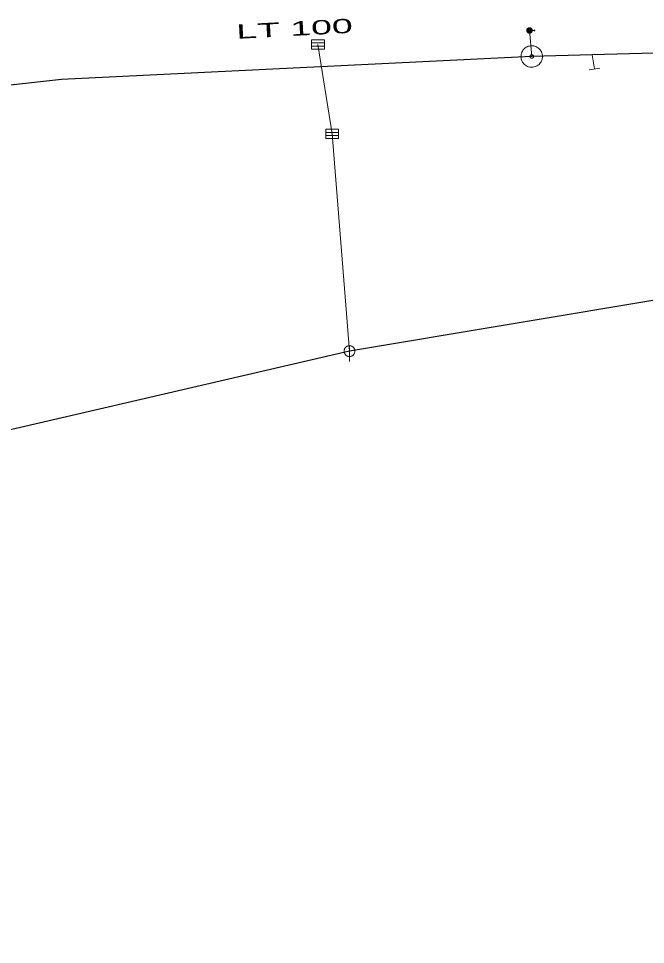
# Model space of a CAD drawing. Extents: x -687515 to -686506, y -974029 to -973461.
# Drawn here: x -686720.18 to -686691.06, y -973717.75 to -973674.72 of the extents above; entities that cross this region are included whole.
import ezdxf
from ezdxf.enums import TextEntityAlignment as Align

# ---------------------------------------------------------------- set-up
doc = ezdxf.new("R2010")
doc.units = 0
doc.header["$LTSCALE"] = 0.27
for name, color, linetype, lineweight in [('1', 7, 'Continuous', 13), ('11', 7, 'Continuous', 13), ('14', 7, 'Continuous', 25), ('17', 7, 'Continuous', 25), ('22', 7, 'Continuous', 13), ('34', 7, 'Continuous', 13), ('47', 7, 'Continuous', 13), ('9', 7, 'Continuous', 13)]:
    doc.layers.add(name, color=color, linetype=linetype, lineweight=lineweight)

msp = doc.modelspace()

# ---------------------------------------------------------------- linework, layer by layer
at = {"layer": '11'}
msp.add_lwpolyline([(-686706.28, -973675.92), (-686705.62, -973680.08), (-686704.81, -973690.17)], dxfattribs=at)
at = {"layer": '14', "lineweight": 13}
for p, q in [((-686696.345, -973676.48), (-686696.449, -973675.269)), ((-686693.532, -973676.405), (-686693.429, -973677.059))]:
    msp.add_line(p, q, dxfattribs=at)
at = {"layer": '14'}
for p, q in [((-686672.372, -973684.756), (-686704.809, -973690.17)), ((-686704.809, -973690.17), (-686742.511, -973698.919))]:
    msp.add_line(p, q, dxfattribs=at)
at = {"layer": '17'}
for points in [[(-686506.346, -973717.746), (-686529.344, -973710.524), (-686536.247, -973707.872), (-686555.026, -973699.577), (-686572.978, -973698.129), (-686583.112, -973698.418), (-686615.962, -973695.359), (-686637.993, -973681.581), (-686653.818, -973675.34), (-686693.532, -973676.405), (-686696.345, -973676.48)], [(-686696.345, -973676.48), (-686718.181, -973677.546), (-686724.343, -973678.231)]]:
    msp.add_lwpolyline(points, dxfattribs=at)
at = {"layer": '22'}
for p, q in [((-686706.575, -973675.849), (-686705.977, -973675.849)), ((-686706.575, -973675.995), (-686705.977, -973675.995)), ((-686705.915, -973680.009), (-686705.317, -973680.009)), ((-686705.915, -973680.154), (-686705.317, -973680.154)), ((-686704.809, -973689.918), (-686704.81, -973690.662))]:
    msp.add_line(p, q, dxfattribs=at)
for points in [[(-686706.575, -973675.703), (-686705.977, -973675.703), (-686705.977, -973676.14), (-686706.575, -973676.14)], [(-686705.915, -973679.863), (-686705.317, -973679.863), (-686705.317, -973680.299), (-686705.915, -973680.299)], [(-686704.558, -973690.17), (-686704.559, -973690.144), (-686704.563, -973690.118), (-686704.569, -973690.092), (-686704.579, -973690.068), (-686704.591, -973690.044), (-686704.605, -973690.022), (-686704.622, -973690.001), (-686704.64, -973689.983), (-686704.661, -973689.966), (-686704.683, -973689.952), (-686704.707, -973689.94), (-686704.731, -973689.93), (-686704.757, -973689.924), (-686704.783, -973689.92), (-686704.809, -973689.918), (-686704.835, -973689.919), (-686704.861, -973689.923), (-686704.887, -973689.929), (-686704.912, -973689.939), (-686704.935, -973689.951), (-686704.957, -973689.965), (-686704.978, -973689.982), (-686704.996, -973690), (-686705.013, -973690.021), (-686705.027, -973690.043), (-686705.039, -973690.067), (-686705.049, -973690.091), (-686705.056, -973690.117), (-686705.06, -973690.143), (-686705.062, -973690.169), (-686705.061, -973690.195), (-686705.057, -973690.221), (-686705.05, -973690.247), (-686705.04, -973690.272), (-686705.028, -973690.295), (-686705.014, -973690.317), (-686704.997, -973690.338), (-686704.979, -973690.356), (-686704.958, -973690.373), (-686704.936, -973690.387), (-686704.913, -973690.399), (-686704.888, -973690.409), (-686704.862, -973690.416), (-686704.836, -973690.42), (-686704.81, -973690.422), (-686704.784, -973690.421), (-686704.758, -973690.417), (-686704.732, -973690.41), (-686704.708, -973690.4), (-686704.684, -973690.388), (-686704.662, -973690.374), (-686704.641, -973690.357), (-686704.623, -973690.339), (-686704.606, -973690.318), (-686704.592, -973690.296), (-686704.58, -973690.273), (-686704.57, -973690.248), (-686704.564, -973690.222), (-686704.56, -973690.196)]]:
    msp.add_lwpolyline(points, close=True, dxfattribs=at)
at = {"layer": '34'}
msp.add_line((-686693.674, -973677.097), (-686693.183, -973677.02), dxfattribs=at)
at = {"layer": '47'}
for points in [[(-686695.885, -973676.676), (-686695.867, -973676.627), (-686695.854, -973676.576), (-686695.847, -973676.524), (-686695.844, -973676.472), (-686695.848, -973676.42), (-686695.858, -973676.368), (-686695.872, -973676.318), (-686695.892, -973676.269), (-686695.915, -973676.223), (-686695.945, -973676.179), (-686695.978, -973676.139), (-686696.016, -973676.103), (-686696.057, -973676.071), (-686696.102, -973676.043), (-686696.148, -973676.02), (-686696.197, -973676.002), (-686696.248, -973675.989), (-686696.301, -973675.982), (-686696.352, -973675.979), (-686696.404, -973675.983), (-686696.456, -973675.993), (-686696.507, -973676.007), (-686696.555, -973676.026), (-686696.602, -973676.05), (-686696.645, -973676.08), (-686696.685, -973676.113), (-686696.722, -973676.151), (-686696.753, -973676.192), (-686696.781, -973676.237), (-686696.804, -973676.283), (-686696.822, -973676.332), (-686696.835, -973676.383), (-686696.843, -973676.435), (-686696.845, -973676.487), (-686696.841, -973676.539), (-686696.832, -973676.591), (-686696.818, -973676.642), (-686696.799, -973676.69), (-686696.774, -973676.737), (-686696.744, -973676.78), (-686696.711, -973676.82), (-686696.674, -973676.856), (-686696.632, -973676.888), (-686696.587, -973676.916), (-686696.541, -973676.939), (-686696.492, -973676.957), (-686696.441, -973676.97), (-686696.39, -973676.978), (-686696.337, -973676.98), (-686696.285, -973676.976), (-686696.233, -973676.967), (-686696.183, -973676.953), (-686696.135, -973676.933), (-686696.088, -973676.909), (-686696.044, -973676.879), (-686696.004, -973676.846), (-686695.969, -973676.809), (-686695.936, -973676.767), (-686695.908, -973676.722)], [(-686696.269, -973676.512), (-686696.266, -973676.503), (-686696.264, -973676.495), (-686696.263, -973676.487), (-686696.263, -973676.479), (-686696.263, -973676.47), (-686696.265, -973676.461), (-686696.267, -973676.453), (-686696.27, -973676.445), (-686696.274, -973676.438), (-686696.279, -973676.43), (-686696.285, -973676.423), (-686696.291, -973676.418), (-686696.297, -973676.413), (-686696.304, -973676.408), (-686696.312, -973676.404), (-686696.321, -973676.401), (-686696.329, -973676.399), (-686696.337, -973676.398), (-686696.345, -973676.398), (-686696.354, -973676.398), (-686696.363, -973676.4), (-686696.371, -973676.402), (-686696.379, -973676.405), (-686696.387, -973676.409), (-686696.394, -973676.414), (-686696.401, -973676.42), (-686696.406, -973676.426), (-686696.411, -973676.432), (-686696.416, -973676.439), (-686696.42, -973676.447), (-686696.423, -973676.456), (-686696.425, -973676.464), (-686696.426, -973676.472), (-686696.426, -973676.48), (-686696.426, -973676.489), (-686696.425, -973676.497), (-686696.422, -973676.506), (-686696.419, -973676.514), (-686696.415, -973676.522), (-686696.41, -973676.529), (-686696.404, -973676.536), (-686696.398, -973676.541), (-686696.392, -973676.546), (-686696.385, -973676.551), (-686696.377, -973676.555), (-686696.368, -973676.558), (-686696.36, -973676.56), (-686696.352, -973676.561), (-686696.344, -973676.561), (-686696.335, -973676.561), (-686696.327, -973676.56), (-686696.318, -973676.557), (-686696.31, -973676.554), (-686696.303, -973676.55), (-686696.295, -973676.545), (-686696.288, -973676.539), (-686696.283, -973676.533), (-686696.278, -973676.527), (-686696.273, -973676.52)]]:
    msp.add_lwpolyline(points, close=True, dxfattribs=at)
at = {"layer": '9'}
msp.add_line((-686696.323, -973675.269), (-686696.197, -973675.269), dxfattribs=at)
for points in [[(-686696.449, -973675.395), (-686696.436, -973675.394), (-686696.423, -973675.392), (-686696.41, -973675.389), (-686696.398, -973675.384), (-686696.386, -973675.378), (-686696.375, -973675.371), (-686696.365, -973675.363), (-686696.355, -973675.353), (-686696.347, -973675.343), (-686696.34, -973675.332), (-686696.334, -973675.32), (-686696.329, -973675.308), (-686696.326, -973675.295), (-686696.324, -973675.282), (-686696.323, -973675.269), (-686696.323, -973675.256), (-686696.325, -973675.243), (-686696.328, -973675.23), (-686696.333, -973675.218), (-686696.339, -973675.206), (-686696.346, -973675.195), (-686696.354, -973675.185), (-686696.364, -973675.175), (-686696.374, -973675.167), (-686696.385, -973675.16), (-686696.397, -973675.154), (-686696.409, -973675.149), (-686696.422, -973675.146), (-686696.435, -973675.144), (-686696.448, -973675.142), (-686696.461, -973675.143), (-686696.474, -973675.145), (-686696.487, -973675.148), (-686696.499, -973675.153), (-686696.511, -973675.159), (-686696.522, -973675.166), (-686696.532, -973675.174), (-686696.542, -973675.184), (-686696.55, -973675.194), (-686696.557, -973675.205), (-686696.563, -973675.217), (-686696.568, -973675.229), (-686696.571, -973675.242), (-686696.573, -973675.255), (-686696.575, -973675.268), (-686696.574, -973675.281), (-686696.572, -973675.294), (-686696.569, -973675.307), (-686696.564, -973675.319), (-686696.558, -973675.331), (-686696.551, -973675.342), (-686696.543, -973675.352), (-686696.533, -973675.362), (-686696.523, -973675.37), (-686696.512, -973675.377), (-686696.5, -973675.383), (-686696.488, -973675.388), (-686696.475, -973675.391), (-686696.462, -973675.393)], [(-686696.449, -973675.375), (-686696.438, -973675.375), (-686696.427, -973675.373), (-686696.416, -973675.37), (-686696.406, -973675.366), (-686696.396, -973675.361), (-686696.387, -973675.355), (-686696.378, -973675.348), (-686696.37, -973675.34), (-686696.363, -973675.331), (-686696.357, -973675.322), (-686696.352, -973675.312), (-686696.348, -973675.302), (-686696.345, -973675.291), (-686696.343, -973675.28), (-686696.343, -973675.269), (-686696.342, -973675.258), (-686696.344, -973675.247), (-686696.347, -973675.236), (-686696.351, -973675.226), (-686696.356, -973675.216), (-686696.362, -973675.207), (-686696.369, -973675.198), (-686696.377, -973675.19), (-686696.386, -973675.183), (-686696.395, -973675.177), (-686696.405, -973675.172), (-686696.415, -973675.168), (-686696.426, -973675.165), (-686696.437, -973675.163), (-686696.448, -973675.163), (-686696.459, -973675.162), (-686696.47, -973675.164), (-686696.481, -973675.167), (-686696.491, -973675.171), (-686696.501, -973675.176), (-686696.51, -973675.182), (-686696.519, -973675.189), (-686696.527, -973675.197), (-686696.534, -973675.206), (-686696.54, -973675.215), (-686696.545, -973675.225), (-686696.549, -973675.235), (-686696.552, -973675.246), (-686696.554, -973675.257), (-686696.555, -973675.268), (-686696.555, -973675.279), (-686696.553, -973675.29), (-686696.55, -973675.301), (-686696.546, -973675.311), (-686696.541, -973675.321), (-686696.535, -973675.33), (-686696.528, -973675.339), (-686696.52, -973675.347), (-686696.511, -973675.354), (-686696.502, -973675.36), (-686696.492, -973675.365), (-686696.482, -973675.369), (-686696.471, -973675.372), (-686696.46, -973675.374)], [(-686696.449, -973675.356), (-686696.44, -973675.355), (-686696.431, -973675.354), (-686696.422, -973675.351), (-686696.414, -973675.348), (-686696.406, -973675.344), (-686696.398, -973675.339), (-686696.391, -973675.333), (-686696.385, -973675.327), (-686696.379, -973675.32), (-686696.374, -973675.312), (-686696.37, -973675.304), (-686696.367, -973675.296), (-686696.364, -973675.287), (-686696.363, -973675.278), (-686696.362, -973675.269), (-686696.362, -973675.26), (-686696.363, -973675.251), (-686696.366, -973675.242), (-686696.369, -973675.234), (-686696.373, -973675.226), (-686696.378, -973675.218), (-686696.384, -973675.211), (-686696.39, -973675.205), (-686696.397, -973675.199), (-686696.405, -973675.194), (-686696.413, -973675.19), (-686696.421, -973675.187), (-686696.43, -973675.184), (-686696.439, -973675.183), (-686696.448, -973675.181), (-686696.457, -973675.182), (-686696.466, -973675.183), (-686696.475, -973675.186), (-686696.483, -973675.189), (-686696.491, -973675.193), (-686696.499, -973675.198), (-686696.506, -973675.204), (-686696.512, -973675.21), (-686696.518, -973675.217), (-686696.523, -973675.225), (-686696.527, -973675.233), (-686696.53, -973675.241), (-686696.533, -973675.25), (-686696.534, -973675.259), (-686696.536, -973675.268), (-686696.535, -973675.277), (-686696.534, -973675.286), (-686696.531, -973675.295), (-686696.528, -973675.303), (-686696.524, -973675.311), (-686696.519, -973675.319), (-686696.513, -973675.326), (-686696.507, -973675.332), (-686696.5, -973675.338), (-686696.492, -973675.343), (-686696.484, -973675.347), (-686696.476, -973675.35), (-686696.467, -973675.353), (-686696.458, -973675.354)], [(-686696.449, -973675.336), (-686696.442, -973675.336), (-686696.435, -973675.334), (-686696.428, -973675.333), (-686696.422, -973675.33), (-686696.416, -973675.327), (-686696.41, -973675.323), (-686696.404, -973675.319), (-686696.399, -973675.314), (-686696.395, -973675.308), (-686696.391, -973675.302), (-686696.388, -973675.296), (-686696.385, -973675.29), (-686696.384, -973675.283), (-686696.382, -973675.276), (-686696.382, -973675.269), (-686696.381, -973675.262), (-686696.383, -973675.255), (-686696.384, -973675.248), (-686696.387, -973675.242), (-686696.39, -973675.235), (-686696.394, -973675.23), (-686696.398, -973675.224), (-686696.403, -973675.219), (-686696.409, -973675.215), (-686696.415, -973675.211), (-686696.421, -973675.208), (-686696.427, -973675.205), (-686696.434, -973675.203), (-686696.441, -973675.202), (-686696.448, -973675.201), (-686696.455, -973675.201), (-686696.462, -973675.202), (-686696.469, -973675.204), (-686696.475, -973675.207), (-686696.482, -973675.21), (-686696.487, -973675.214), (-686696.493, -973675.218), (-686696.498, -973675.223), (-686696.502, -973675.229), (-686696.506, -973675.234), (-686696.509, -973675.241), (-686696.512, -973675.247), (-686696.514, -973675.254), (-686696.515, -973675.261), (-686696.516, -973675.268), (-686696.516, -973675.275), (-686696.515, -973675.282), (-686696.513, -973675.289), (-686696.51, -973675.295), (-686696.507, -973675.301), (-686696.503, -973675.307), (-686696.499, -973675.313), (-686696.494, -973675.318), (-686696.488, -973675.322), (-686696.483, -973675.326), (-686696.476, -973675.329), (-686696.47, -973675.332), (-686696.463, -973675.333), (-686696.456, -973675.335)], [(-686696.449, -973675.316), (-686696.444, -973675.316), (-686696.439, -973675.315), (-686696.434, -973675.314), (-686696.43, -973675.312), (-686696.425, -973675.31), (-686696.421, -973675.307), (-686696.418, -973675.304), (-686696.414, -973675.3), (-686696.411, -973675.297), (-686696.408, -973675.293), (-686696.406, -973675.288), (-686696.404, -973675.284), (-686696.403, -973675.279), (-686696.402, -973675.274), (-686696.402, -973675.269), (-686696.401, -973675.264), (-686696.402, -973675.259), (-686696.403, -973675.254), (-686696.405, -973675.25), (-686696.407, -973675.245), (-686696.41, -973675.241), (-686696.413, -973675.237), (-686696.417, -973675.234), (-686696.42, -973675.231), (-686696.424, -973675.228), (-686696.429, -973675.226), (-686696.433, -973675.224), (-686696.438, -973675.223), (-686696.443, -973675.222), (-686696.448, -973675.222), (-686696.453, -973675.221), (-686696.458, -973675.222), (-686696.463, -973675.223), (-686696.467, -973675.225), (-686696.472, -973675.227), (-686696.476, -973675.23), (-686696.48, -973675.233), (-686696.483, -973675.236), (-686696.486, -973675.24), (-686696.489, -973675.244), (-686696.491, -973675.249), (-686696.493, -973675.253), (-686696.494, -973675.258), (-686696.495, -973675.263), (-686696.496, -973675.268), (-686696.496, -973675.273), (-686696.495, -973675.278), (-686696.494, -973675.283), (-686696.492, -973675.287), (-686696.49, -973675.292), (-686696.487, -973675.296), (-686696.484, -973675.299), (-686696.481, -973675.303), (-686696.477, -973675.306), (-686696.473, -973675.309), (-686696.468, -973675.311), (-686696.464, -973675.313), (-686696.459, -973675.314), (-686696.454, -973675.315)], [(-686696.449, -973675.296), (-686696.446, -973675.296), (-686696.443, -973675.296), (-686696.441, -973675.295), (-686696.438, -973675.294), (-686696.435, -973675.293), (-686696.433, -973675.291), (-686696.431, -973675.289), (-686696.429, -973675.287), (-686696.427, -973675.285), (-686696.425, -973675.283), (-686696.424, -973675.28), (-686696.423, -973675.277), (-686696.422, -973675.275), (-686696.422, -973675.272), (-686696.422, -973675.269), (-686696.421, -973675.266), (-686696.421, -973675.263), (-686696.422, -973675.26), (-686696.423, -973675.258), (-686696.424, -973675.255), (-686696.426, -973675.253), (-686696.428, -973675.25), (-686696.43, -973675.248), (-686696.432, -973675.247), (-686696.434, -973675.245), (-686696.437, -973675.244), (-686696.44, -973675.243), (-686696.442, -973675.242), (-686696.445, -973675.242), (-686696.448, -973675.24), (-686696.451, -973675.241), (-686696.454, -973675.241), (-686696.457, -973675.242), (-686696.459, -973675.243), (-686696.462, -973675.244), (-686696.464, -973675.246), (-686696.467, -973675.247), (-686696.469, -973675.249), (-686696.47, -973675.252), (-686696.472, -973675.254), (-686696.473, -973675.257), (-686696.474, -973675.259), (-686696.475, -973675.262), (-686696.475, -973675.265), (-686696.477, -973675.268), (-686696.476, -973675.271), (-686696.476, -973675.274), (-686696.475, -973675.276), (-686696.474, -973675.279), (-686696.473, -973675.282), (-686696.471, -973675.284), (-686696.47, -973675.286), (-686696.468, -973675.288), (-686696.465, -973675.29), (-686696.463, -973675.292), (-686696.46, -973675.293), (-686696.458, -973675.294), (-686696.455, -973675.295), (-686696.452, -973675.295)], [(-686696.449, -973675.277), (-686696.448, -973675.277), (-686696.447, -973675.277), (-686696.447, -973675.276), (-686696.446, -973675.276), (-686696.445, -973675.276), (-686696.444, -973675.275), (-686696.444, -973675.275), (-686696.443, -973675.274), (-686696.443, -973675.274), (-686696.442, -973675.273), (-686696.442, -973675.272), (-686696.442, -973675.271), (-686696.441, -973675.271), (-686696.441, -973675.27), (-686696.441, -973675.269), (-686696.441, -973675.268), (-686696.441, -973675.267), (-686696.441, -973675.267), (-686696.441, -973675.266), (-686696.441, -973675.265), (-686696.442, -973675.264), (-686696.442, -973675.264), (-686696.443, -973675.263), (-686696.443, -973675.263), (-686696.444, -973675.262), (-686696.445, -973675.262), (-686696.446, -973675.261), (-686696.446, -973675.261), (-686696.447, -973675.261), (-686696.448, -973675.261), (-686696.449, -973675.261), (-686696.45, -973675.261), (-686696.45, -973675.261), (-686696.451, -973675.261), (-686696.452, -973675.261), (-686696.453, -973675.262), (-686696.453, -973675.262), (-686696.454, -973675.263), (-686696.454, -973675.263), (-686696.455, -973675.264), (-686696.455, -973675.265), (-686696.456, -973675.266), (-686696.456, -973675.266), (-686696.456, -973675.267), (-686696.457, -973675.268), (-686696.457, -973675.269), (-686696.457, -973675.27), (-686696.457, -973675.27), (-686696.456, -973675.271), (-686696.456, -973675.272), (-686696.455, -973675.273), (-686696.455, -973675.273), (-686696.454, -973675.274), (-686696.454, -973675.274), (-686696.453, -973675.275), (-686696.452, -973675.275), (-686696.451, -973675.275), (-686696.451, -973675.276), (-686696.45, -973675.276)]]:
    msp.add_lwpolyline(points, close=True, dxfattribs=at)
msp.add_lwpolyline([(-686696.231, -973675.238), (-686696.197, -973675.269), (-686696.232, -973675.3)], dxfattribs=at)

# ---------------------------------------------------------------- texts
at = {"layer": '1', "width": 1.95}
msp.add_text('LT 100', height=0.6667, rotation=3, dxfattribs=at).set_placement((-686707.348, -973675.519), align=Align.CENTER)

doc.saveas('drawing.dxf')
